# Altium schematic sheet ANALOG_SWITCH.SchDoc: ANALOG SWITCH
size A3; Author: Silvio Navaretti; CompanyName: ARDUINO; DrawnBy: Silvio Navaretti; Engineer: Silvio Navaretti; Organization: ARDUINO; SheetNumber: 17; SheetTotal: 51; RevAuthor: Silvio Navaretti
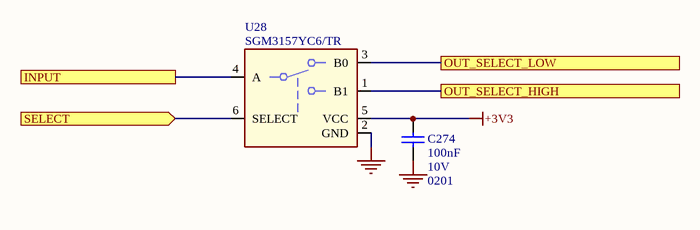
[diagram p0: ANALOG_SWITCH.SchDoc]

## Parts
C274  value 100nF  Voltage: 10V  Case Code (Imperial): 0201  [CAP-0201]  (hidden comment: CL03A104KP3NNNC)
U28  SGM3157YC6/TR  [TSOP65P210X110-6N]

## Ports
INPUT, OUT_SELECT_HIGH, OUT_SELECT_LOW, SELECT (in)

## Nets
+3V3: C274.2 U28.5(VCC)
GND: C274.1 U28.2(GND)
INPUT: U28.4(A) ; port INPUT
OUT_SELECT_HIGH: U28.1(B1) ; port OUT_SELECT_HIGH
OUT_SELECT_LOW: U28.3(B0) ; port OUT_SELECT_LOW
SELECT: U28.6(SELECT) ; port SELECT

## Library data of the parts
C274 = C0113-A.6: CAP CHIP 0201 100nF 10% 10V X5R; Manufacturer: Samsung Electro-Mechanics; Code Arduino: C0113
U28 = U0174-A.3: IC SPDT,max 25R at VCC 4.5V tPD 1.2ns VCC 1.65V to 5V Iq max 10uA SOT363; Manufacturer: SG Micro; Code Arduino: U0174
